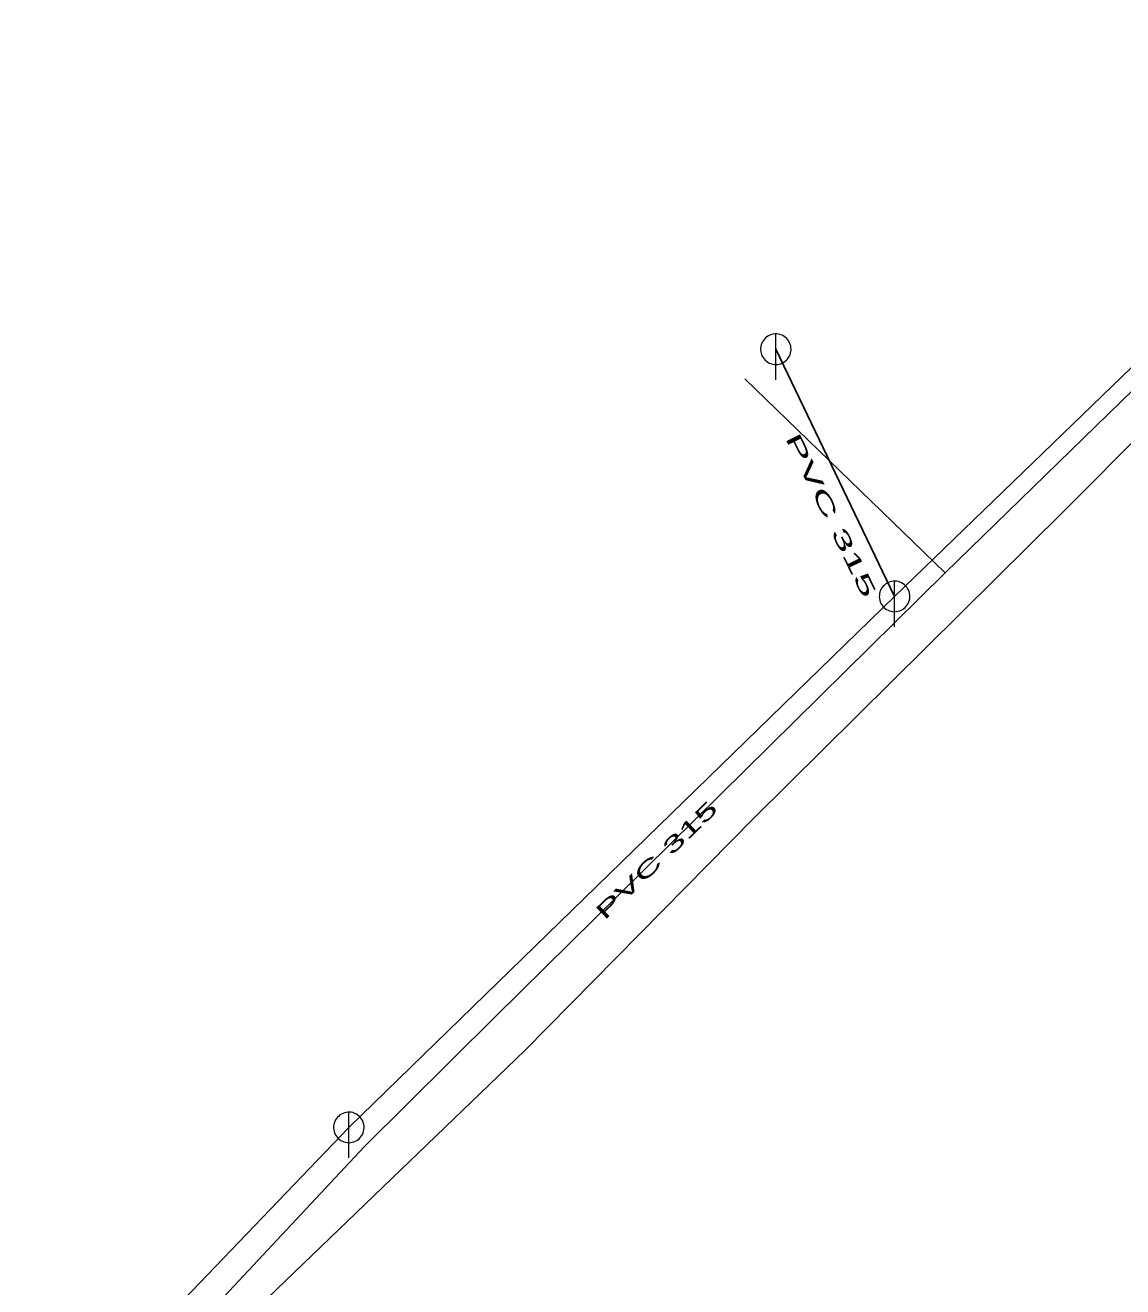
# Model space of a CAD drawing. Extents: x -807203 to -805207, y -993656 to -992505.
# Drawn here: x -806698.4 to -806626.5, y -992964 to -992881.3 of the extents above; entities that cross this region are included whole.
import ezdxf

# ---------------------------------------------------------------- set-up
doc = ezdxf.new("R2010")
doc.units = 0
doc.header["$LTSCALE"] = 0.4
for name, color, linetype, lineweight in [('1', 7, 'Continuous', 13), ('13', 7, 'Continuous', 13), ('14', 7, 'Continuous', 25), ('17', 7, 'Continuous', 25), ('22', 7, 'Continuous', 13)]:
    doc.layers.add(name, color=color, linetype=linetype, lineweight=lineweight)

msp = doc.modelspace()

# ---------------------------------------------------------------- linework, layer by layer
at = {"layer": '13'}
msp.add_line((-806638.16, -992917.22), (-806651.28, -992904.52), dxfattribs=at)
at = {"layer": '14'}
for p, q in [((-806605.559, -992884.039), (-806641.469, -992918.76)), ((-806649.25, -992902.57), (-806641.469, -992918.76)), ((-806641.469, -992918.76), (-806677.219, -992953.539)), ((-806677.219, -992953.539), (-806699.85, -992977.12))]:
    msp.add_line(p, q, dxfattribs=at)
msp.add_lwpolyline([(-806661.839, -993034.149), (-806676.42, -993009.03), (-806687.16, -992991.6), (-806684.379, -992974.399), (-806682.55, -992964.73), (-806665.699, -992948.5), (-806650.699, -992933.289), (-806630.39, -992913.17), (-806613.82, -992896.559), (-806592.899, -992877.32), (-806567.719, -992852.94), (-806551.12, -992836.629), (-806563.8, -992821.69), (-806562.329, -992819.699), (-806552.96, -992810.51), (-806551.289, -992809.149), (-806548.55, -992808.109), (-806545.73, -992809.739), (-806532.96, -992817.94), (-806527.999, -992817.239)], dxfattribs=at)
at = {"layer": '17'}
msp.add_lwpolyline([(-806698.289, -992977.488), (-806696.94, -992976.539), (-806688.559, -992968), (-806676.219, -992954.809), (-806667.649, -992946.309), (-806638.16, -992917.219), (-806606.07, -992885.989)], dxfattribs=at)
at = {"layer": '22'}
for p, q in [((-806649.25, -992904.57), (-806649.249, -992901.57)), ((-806641.469, -992920.76), (-806641.468, -992917.76)), ((-806677.219, -992955.539), (-806677.218, -992952.539))]:
    msp.add_line(p, q, dxfattribs=at)
for points in [[(-806648.25, -992902.57), (-806648.255, -992902.461), (-806648.273, -992902.353), (-806648.303, -992902.247), (-806648.343, -992902.146), (-806648.395, -992902.049), (-806648.457, -992901.959), (-806648.529, -992901.876), (-806648.609, -992901.802), (-806648.697, -992901.736), (-806648.791, -992901.681), (-806648.891, -992901.636), (-806648.996, -992901.603), (-806649.103, -992901.581), (-806649.212, -992901.571), (-806649.322, -992901.573), (-806649.43, -992901.587), (-806649.537, -992901.612), (-806649.64, -992901.649), (-806649.738, -992901.698), (-806649.83, -992901.756), (-806649.916, -992901.825), (-806649.993, -992901.902), (-806650.062, -992901.988), (-806650.121, -992902.08), (-806650.169, -992902.178), (-806650.206, -992902.281), (-806650.232, -992902.388), (-806650.246, -992902.496), (-806650.249, -992902.606), (-806650.239, -992902.715), (-806650.218, -992902.822), (-806650.184, -992902.926), (-806650.14, -992903.026), (-806650.085, -992903.121), (-806650.019, -992903.209), (-806649.945, -992903.289), (-806649.862, -992903.361), (-806649.772, -992903.423), (-806649.676, -992903.475), (-806649.574, -992903.516), (-806649.469, -992903.546), (-806649.361, -992903.564), (-806649.251, -992903.57), (-806649.142, -992903.564), (-806649.034, -992903.546), (-806648.929, -992903.517), (-806648.827, -992903.476), (-806648.73, -992903.424), (-806648.64, -992903.362), (-806648.557, -992903.291), (-806648.482, -992903.211), (-806648.417, -992903.123), (-806648.361, -992903.029), (-806648.317, -992902.929), (-806648.283, -992902.825), (-806648.261, -992902.717), (-806648.251, -992902.608)], [(-806640.469, -992918.76), (-806640.474, -992918.651), (-806640.492, -992918.543), (-806640.522, -992918.437), (-806640.562, -992918.336), (-806640.614, -992918.239), (-806640.676, -992918.149), (-806640.748, -992918.066), (-806640.828, -992917.992), (-806640.916, -992917.926), (-806641.01, -992917.871), (-806641.11, -992917.826), (-806641.215, -992917.793), (-806641.322, -992917.771), (-806641.431, -992917.761), (-806641.541, -992917.763), (-806641.649, -992917.777), (-806641.756, -992917.802), (-806641.859, -992917.839), (-806641.957, -992917.888), (-806642.049, -992917.946), (-806642.135, -992918.015), (-806642.212, -992918.092), (-806642.281, -992918.178), (-806642.34, -992918.27), (-806642.388, -992918.368), (-806642.425, -992918.471), (-806642.451, -992918.578), (-806642.465, -992918.686), (-806642.468, -992918.796), (-806642.458, -992918.905), (-806642.437, -992919.012), (-806642.403, -992919.116), (-806642.359, -992919.216), (-806642.304, -992919.311), (-806642.238, -992919.399), (-806642.164, -992919.479), (-806642.081, -992919.551), (-806641.991, -992919.613), (-806641.895, -992919.665), (-806641.793, -992919.706), (-806641.688, -992919.736), (-806641.58, -992919.754), (-806641.47, -992919.76), (-806641.361, -992919.754), (-806641.253, -992919.736), (-806641.148, -992919.707), (-806641.046, -992919.666), (-806640.949, -992919.614), (-806640.859, -992919.552), (-806640.776, -992919.481), (-806640.701, -992919.401), (-806640.636, -992919.313), (-806640.58, -992919.219), (-806640.536, -992919.119), (-806640.502, -992919.015), (-806640.48, -992918.907), (-806640.47, -992918.798)], [(-806676.219, -992953.539), (-806676.224, -992953.43), (-806676.242, -992953.322), (-806676.272, -992953.216), (-806676.312, -992953.115), (-806676.364, -992953.018), (-806676.426, -992952.928), (-806676.498, -992952.845), (-806676.578, -992952.771), (-806676.666, -992952.705), (-806676.76, -992952.65), (-806676.86, -992952.605), (-806676.965, -992952.572), (-806677.072, -992952.55), (-806677.181, -992952.54), (-806677.291, -992952.542), (-806677.399, -992952.556), (-806677.506, -992952.581), (-806677.609, -992952.618), (-806677.707, -992952.667), (-806677.799, -992952.725), (-806677.885, -992952.794), (-806677.962, -992952.871), (-806678.031, -992952.957), (-806678.09, -992953.049), (-806678.138, -992953.147), (-806678.175, -992953.25), (-806678.201, -992953.357), (-806678.215, -992953.465), (-806678.218, -992953.575), (-806678.208, -992953.684), (-806678.187, -992953.791), (-806678.153, -992953.895), (-806678.109, -992953.995), (-806678.054, -992954.09), (-806677.988, -992954.178), (-806677.914, -992954.258), (-806677.831, -992954.33), (-806677.741, -992954.392), (-806677.645, -992954.444), (-806677.543, -992954.485), (-806677.438, -992954.515), (-806677.33, -992954.533), (-806677.22, -992954.539), (-806677.111, -992954.533), (-806677.003, -992954.515), (-806676.898, -992954.486), (-806676.796, -992954.445), (-806676.699, -992954.393), (-806676.609, -992954.331), (-806676.526, -992954.26), (-806676.451, -992954.18), (-806676.386, -992954.092), (-806676.33, -992953.998), (-806676.286, -992953.898), (-806676.252, -992953.794), (-806676.23, -992953.686), (-806676.22, -992953.577)]]:
    msp.add_lwpolyline(points, close=True, dxfattribs=at)

# ---------------------------------------------------------------- texts
at = {"layer": '1'}
for rotation, width, p in [(296, 2.2, (-806648.664, -992908.369)), (44, 1.95, (-806660.469, -992940.012))]:
    msp.add_text('PVC 315 ', height=1, rotation=rotation, dxfattribs=dict(at, width=width)).set_placement(p)

doc.saveas('drawing.dxf')
